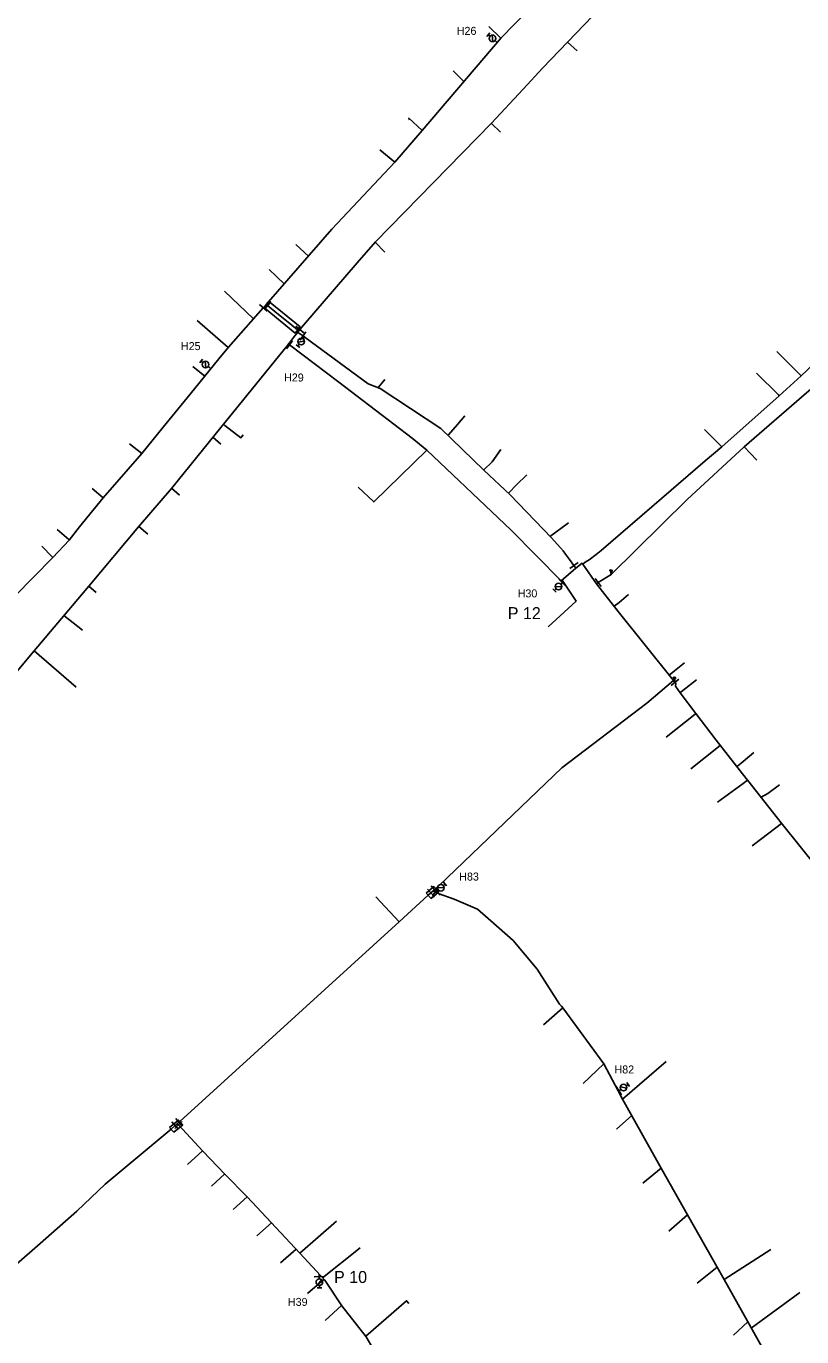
# Model space of a CAD drawing. Extents: x -548873 to -538270, y -1201997 to -1192514.
# Drawn here: x -547306.8 to -547113, y -1195818 to -1195490.5 of the extents above; entities that cross this region are included whole.
import ezdxf

# ---------------------------------------------------------------- set-up
doc = ezdxf.new("R2010")
doc.units = 0
for name, color, linetype in [('KN_HRAN_STÁTNÍ', 7, 'Continuous'), ('KN_PARC_Č', 7, 'Continuous'), ('KN_VKP_HRAN_SPORNÁ', 7, 'Continuous'), ('PK_PARC_Čv', 7, 'Continuous'), ('Vrstva 29', 7, 'Continuous'), ('Vrstva 37', 7, 'Continuous'), ('Vrstva 39', 7, 'Continuous')]:
    doc.layers.add(name, color=color, linetype=linetype)

# ---------------------------------------------------------------- blocks, each defined once
blk = doc.blocks.new('160')
at = {"layer": 'KN_HRAN_STÁTNÍ'}
blk.add_circle((0, 0), 0.0458, dxfattribs=at)
blk = doc.blocks.new('147')
at = {"layer": 'KN_HRAN_STÁTNÍ'}
blk.add_line((0, 1.27), (0, -1.27), dxfattribs=at)
blk = doc.blocks.new('133')
at = {"layer": 'KN_HRAN_STÁTNÍ'}
for p, q in [((0.28, 0), (0, 0)), ((0.54, 0.58), (1.7, -0.58)), ((1.94, 0), (2.52, 0)), ((2.52, 0.58), (2.52, -0.58))]:
    blk.add_line(p, q, dxfattribs=at)
blk.add_circle((1.11, 0), 0.825, dxfattribs=at)
blk = doc.blocks.new('150')
at = {"layer": 'KN_HRAN_STÁTNÍ'}
blk.add_line((0, 1.27), (0, -1.27), dxfattribs=at)
blk = doc.blocks.new('128')
at = {"layer": 'KN_HRAN_STÁTNÍ'}
for p, q in [((-0.19, 1.06), (-0.43, 1.15)), ((-0.36, 0.84), (-0.19, 1.06)), ((-0.19, 1.06), (-0.02, 1.25)), ((-0.19, 1.06), (0, 0)), ((0.05, 0.95), (-0.19, 1.06)), ((-0.1, 1), (0.41, 0.91)), ((-0.07, 0.82), (0.17, 0.96)), ((0.17, 0.96), (-0.02, 1.13)), ((0.17, 0.96), (0, 0)), ((0.19, 1.21), (0.17, 0.96)), ((0.17, 0.96), (0.38, 1.08)), ((0.36, 0.77), (0.17, 0.96))]:
    blk.add_line(p, q, dxfattribs=at)

msp = doc.modelspace()

# ---------------------------------------------------------------- linework, layer by layer
at = {"layer": 'KN_PARC_Č'}
for points in [[(-547188.157, -1195493.496), (-547191.164, -1195490.57)], [(-547171.484, -1195494.463), (-547169.098, -1195496.683)], [(-547197.389, -1195504.339), (-547200.042, -1195501.672)], [(-547207.846, -1195516.619), (-547211.224, -1195513.439)], [(-547211.006, -1195513.645), (-547211.208, -1195513.866)], [(-547190.525, -1195514.821), (-547188.235, -1195516.991)], [(-547214.683, -1195524.509), (-547218.366, -1195521.395)], [(-547236.248, -1195547.97), (-547239.432, -1195545.051)], [(-547219.586, -1195544.48), (-547217.193, -1195546.978)], [(-547242.278, -1195554.859), (-547246.1, -1195551.344)], [(-547250.005, -1195563.656), (-547257.238, -1195556.764)], [(-547256.303, -1195570.794), (-547264.062, -1195564.051)], [(-547113.076, -1195577.902), (-547113.32, -1195577.63), (-547119.159, -1195571.788)], [(-547262.12, -1195577.937), (-547265.145, -1195575.593)], [(-547118.599, -1195582.875), (-547118.81, -1195582.65), (-547124.265, -1195577.19)], [(-547218.844, -1195580.867), (-547218.77, -1195580.697), (-547217.921, -1195579.725), (-547217.128, -1195578.812)], [(-547257.49, -1195589.982), (-547257.128, -1195590.262), (-547253.117, -1195593.362), (-547252.599, -1195592.662)], [(-547201.391, -1195592.725), (-547201.277, -1195592.602), (-547198.998, -1195590.061), (-547197.133, -1195587.91)], [(-547260.139, -1195593.247), (-547258.16, -1195594.956)], [(-547132.96, -1195595.64), (-547133.15, -1195595.4), (-547137.277, -1195591.271)], [(-547277.917, -1195597.331), (-547280.94, -1195594.853)], [(-547206.662, -1195596.428), (-547219.922, -1195609.405), (-547223.845, -1195605.7)], [(-547192.461, -1195601.464), (-547192.379, -1195601.369), (-547190.34, -1195599.362), (-547188.176, -1195596.329)], [(-547127.391, -1195595.645), (-547124.167, -1195598.929)], [(-547186.253, -1195607.23), (-547186.147, -1195607.116), (-547184.212, -1195605.156), (-547181.648, -1195602.627)], [(-547287.52, -1195608.37), (-547290.321, -1195606.042)], [(-547270.481, -1195605.996), (-547268.448, -1195607.715)], [(-547296.04, -1195618.93), (-547296.17, -1195618.82), (-547299.07, -1195616.294)], [(-547278.677, -1195615.583), (-547276.384, -1195617.447)], [(-547175.823, -1195618.078), (-547175.647, -1195617.909), (-547171.622, -1195614.915), (-547171.26, -1195614.594)], [(-547300.1, -1195623.31), (-547300.23, -1195623.18), (-547302.917, -1195620.483)], [(-547172.848, -1195628.94), (-547169.35, -1195634.196), (-547176.358, -1195640.581)], [(-547291.146, -1195630.415), (-547289.296, -1195632.069)], [(-547159.856, -1195635.438), (-547158.582, -1195634.575), (-547156.257, -1195632.55)], [(-547297.369, -1195637.797), (-547292.745, -1195641.468)], [(-547304.795, -1195646.608), (-547294.298, -1195655.699)], [(-547146.057, -1195652.697), (-547144.769, -1195651.626), (-547142.303, -1195649.588)], [(-547143.317, -1195657.085), (-547143.209, -1195656.982), (-547142.65, -1195656.557), (-547139.304, -1195653.845)], [(-547139.408, -1195662.241), (-547139.619, -1195662.409), (-547146.826, -1195668.214)], [(-547133.312, -1195670.243), (-547140.646, -1195676.08)], [(-547129.144, -1195675.573), (-547129.002, -1195675.464), (-547127.61, -1195674.241), (-547124.906, -1195671.996)], [(-547126.535, -1195678.903), (-547127.613, -1195679.76), (-547134, -1195684.464)], [(-547123.134, -1195683.202), (-547123.113, -1195683.187), (-547121.404, -1195682.295), (-547118.494, -1195680.119)], [(-547117.976, -1195689.726), (-547118.051, -1195689.784), (-547122.973, -1195693.533), (-547125.334, -1195695.381)], [(-547213.599, -1195714.36), (-547219.415, -1195708.069)], [(-547172.631, -1195735.835), (-547177.528, -1195740.059)], [(-547162.403, -1195749.852), (-547167.63, -1195754.735)], [(-547157.729, -1195758.622), (-547146.882, -1195749.273)], [(-547155.43, -1195762.759), (-547159.256, -1195766.13)], [(-547262.724, -1195771.598), (-547266.506, -1195774.984)], [(-547257.184, -1195777.291), (-547260.458, -1195780.425)], [(-547148.114, -1195775.919), (-547152.679, -1195779.619)], [(-547251.561, -1195783.065), (-547255.072, -1195786.255)], [(-547141.551, -1195787.544), (-547146.206, -1195791.646)], [(-547245.509, -1195789.544), (-547249.18, -1195792.849)], [(-547238.429, -1195797.125), (-547229.231, -1195789.178)], [(-547239.326, -1195796.164), (-547243.224, -1195799.576)], [(-547232.695, -1195803.29), (-547223.289, -1195795.794)], [(-547132.37, -1195803.712), (-547120.7, -1195796.19)], [(-547134.121, -1195800.628), (-547139.086, -1195804.636)], [(-547232.352, -1195803.659), (-547236.451, -1195807.204)], [(-547125.58, -1195815.872), (-547113.481, -1195806.965)], [(-547227.95, -1195810.243), (-547232.034, -1195813.991)], [(-547221.938, -1195817.9), (-547211.733, -1195809.037), (-547211.124, -1195809.71)], [(-547126.457, -1195814.301), (-547130, -1195817.611)]]:
    msp.add_lwpolyline(points, dxfattribs=at)
at = {"layer": 'KN_VKP_HRAN_SPORNÁ'}
for points in [[(-547246.799, -1195560.024), (-547230.382, -1195541.268), (-547214.699, -1195524.527), (-547207.817, -1195516.586), (-547188.114, -1195493.446), (-547181.403, -1195486.59), (-547175.033, -1195479.774), (-547167.714, -1195471.913), (-547160.967, -1195464.894), (-547143.297, -1195446.062), (-547136.789, -1195436.389), (-547134.548, -1195432.99), (-547127.853, -1195421.088), (-547118.783, -1195405.857), (-547114.117, -1195398.022)], [(-547132.988, -1195449.593), (-547144.079, -1195462.753), (-547150.381, -1195470.964), (-547159.039, -1195481.415), (-547177.635, -1195500.911), (-547182.589, -1195506.258), (-547190.482, -1195514.777), (-547219.522, -1195544.405), (-547224.042, -1195549.648), (-547237.452, -1195565.2), (-547238.39, -1195566.304)], [(-547160.61, -1195627.54), (-547141.63, -1195608.78), (-547127.359, -1195595.616), (-547111.746, -1195582.119), (-547089.115, -1195562.731), (-547061.579, -1195539.141), (-547058.208, -1195536.47), (-547044.74, -1195525.49), (-547042.872, -1195522.421), (-547039.65, -1195513.61), (-547035.807, -1195503.886), (-547031.746, -1195506.151), (-547016.716, -1195514.537), (-547006.025, -1195520.502), (-546990.119, -1195529.563), (-546969.644, -1195542.866)], [(-547167.71, -1195624.93), (-547167.11, -1195624.49), (-547166.098, -1195623.905), (-547164.377, -1195622.558), (-547163.1, -1195621.56), (-547147.98, -1195608.532), (-547137.07, -1195599.13), (-547132.96, -1195595.64), (-547118.599, -1195582.875), (-547113.099, -1195577.925), (-547111.617, -1195576.495), (-547096.74, -1195562.14), (-547090.42, -1195556.45), (-547087.773, -1195554), (-547080.425, -1195547.036), (-547050.942, -1195519.091), (-547050.01, -1195518.153), (-547049.27, -1195517.41)], [(-547293.43, -1195615.64), (-547287.52, -1195608.37), (-547277.91, -1195597.322), (-547272.536, -1195590.724), (-547265.825, -1195582.485), (-547258.649, -1195573.675), (-547256.256, -1195570.737), (-547247.536, -1195560.859)], [(-547247.536, -1195560.859), (-547246.799, -1195560.024)], [(-547246.799, -1195560.024), (-547246.567, -1195560.214)], [(-547246.567, -1195560.214), (-547244.118, -1195562.214), (-547241.335, -1195564.488), (-547239.48, -1195566.003), (-547238.963, -1195566.426), (-547238.689, -1195566.656)], [(-547238.917, -1195566.981), (-547239.942, -1195568.349), (-547241.246, -1195569.957)], [(-547238.689, -1195566.656), (-547238.917, -1195566.981)], [(-547238.917, -1195566.981), (-547238.672, -1195567.191)], [(-547238.39, -1195566.304), (-547238.689, -1195566.656)], [(-547238.672, -1195567.191), (-547238.669, -1195567.193), (-547237.584, -1195567.929)], [(-547237.584, -1195567.929), (-547237.026, -1195568.307), (-547221.297, -1195579.87), (-547218.359, -1195581.064), (-547203.143, -1195591.01), (-547192.423, -1195601.501), (-547185.821, -1195607.631), (-547175.504, -1195618.411), (-547172.626, -1195621.662), (-547172.019, -1195622.42), (-547171.003, -1195623.81), (-547169.907, -1195625.32)], [(-547241.246, -1195569.957), (-547259.588, -1195592.568), (-547270.51, -1195606.032), (-547278.725, -1195615.639), (-547291.147, -1195630.416), (-547304.795, -1195646.608), (-547316.823, -1195660.848), (-547326.873, -1195671.491), (-547331.512, -1195679.088), (-547337.016, -1195684.424), (-547351.223, -1195698.329), (-547357.069, -1195703.944)], [(-547241.246, -1195569.957), (-547241, -1195570.143)], [(-547241, -1195570.143), (-547228.659, -1195579.474), (-547210.315, -1195593.437), (-547206.664, -1195596.426), (-547185.56, -1195616.44), (-547173.09, -1195629.15), (-547169.431, -1195625.977)], [(-547319.87, -1195643.25), (-547319.38, -1195642.78), (-547300.1, -1195623.31), (-547296.04, -1195618.93), (-547293.43, -1195615.64)], [(-547169.907, -1195625.32), (-547169.431, -1195625.977)], [(-547169.431, -1195625.977), (-547167.881, -1195624.72), (-547167.71, -1195624.93)], [(-547167.71, -1195624.93), (-547164.226, -1195629.833)], [(-547164.226, -1195629.833), (-547163.871, -1195629.544)], [(-547164.226, -1195629.833), (-547159.162, -1195636.328)], [(-547163.871, -1195629.544), (-547160.61, -1195627.54)], [(-547159.162, -1195636.328), (-547145.014, -1195653.999)], [(-547145.014, -1195653.999), (-547151.72, -1195659.69), (-547172.901, -1195675.827), (-547203.578, -1195705.232), (-547204.416, -1195706.032), (-547204.473, -1195706.086), (-547204.735, -1195706.318)], [(-547145.014, -1195653.999), (-547144.779, -1195654.323)], [(-547144.779, -1195654.323), (-547144.665, -1195654.487)], [(-547144.665, -1195654.487), (-547144.454, -1195654.703), (-547144.513, -1195655.474), (-547143.317, -1195657.085), (-547139.408, -1195662.241), (-547134.331, -1195668.939), (-547126.864, -1195678.49), (-547126.412, -1195679.057), (-547119.021, -1195688.403), (-547118.07, -1195689.608), (-547108.983, -1195701.041), (-547101.095, -1195711.038), (-547100.661, -1195711.518), (-547094.705, -1195719.024), (-547087.803, -1195727.655), (-547080.248, -1195737.156), (-547076.81, -1195741.454), (-547069.388, -1195750.676), (-547065.365, -1195755.767), (-547059.201, -1195763.374)], [(-547205.625, -1195707.109), (-547206.305, -1195707.713), (-547213.599, -1195714.36), (-547268.366, -1195764.271), (-547268.604, -1195764.47)], [(-547205.057, -1195706.604), (-547205.625, -1195707.109)], [(-547204.735, -1195706.318), (-547205.057, -1195706.604)], [(-547204.638, -1195706.848), (-547205.057, -1195706.604)], [(-547120.307, -1195825.316), (-547132.374, -1195803.704), (-547141.539, -1195787.566), (-547148.053, -1195776.029), (-547157.729, -1195758.622), (-547158.807, -1195756.6), (-547162.403, -1195749.852), (-547172.652, -1195735.806), (-547172.977, -1195735.453), (-547173.481, -1195734.906), (-547179.072, -1195726.137), (-547185.043, -1195719.013), (-547190.689, -1195714.11), (-547194.018, -1195711.149), (-547199.79, -1195708.655), (-547203.551, -1195707.329), (-547204.028, -1195707.156), (-547204.638, -1195706.848)], [(-547268.604, -1195764.47), (-547268.987, -1195764.792)], [(-547269.561, -1195765.274), (-547270.596, -1195766.141), (-547287.035, -1195779.881), (-547294.101, -1195786.683), (-547303.328, -1195794.687), (-547309.862, -1195800.458), (-547311.869, -1195802.1)], [(-547268.987, -1195764.792), (-547269.561, -1195765.274)], [(-547268.987, -1195764.792), (-547268.716, -1195765.086)], [(-547268.716, -1195765.086), (-547262.663, -1195771.664), (-547257.105, -1195777.372), (-547251.547, -1195783.08), (-547238.429, -1195797.125), (-547232.152, -1195803.874), (-547227.937, -1195810.262), (-547221.839, -1195818.026), (-547216.584, -1195827.046)]]:
    msp.add_lwpolyline(points, dxfattribs=at)
at = {"layer": 'PK_PARC_Čv'}
for points in [[(-547189.051, -1195494.547), (-547189.386, -1195494.261)], [(-547237.231, -1195568.168), (-547237.414, -1195568.421)], [(-547260.632, -1195576.11), (-547261.089, -1195575.75)], [(-547172.541, -1195629.401), (-547172.95, -1195629.79)], [(-547206.8, -1195707.19), (-547204.91, -1195705.51), (-547203.68, -1195706.81), (-547205.57, -1195708.49), (-547206.8, -1195707.19)], [(-547204.408, -1195706.964), (-547203.972, -1195706.576)], [(-547158.807, -1195756.6), (-547158.438, -1195756.365)], [(-547270.97, -1195765.75), (-547268.74, -1195763.88), (-547267.64, -1195765.03), (-547269.87, -1195766.9), (-547270.97, -1195765.75)], [(-547233.551, -1195802.37), (-547233.543, -1195803.022), (-547233.54, -1195803.279)]]:
    msp.add_lwpolyline(points, dxfattribs=at)
at = {"layer": 'Vrstva 37'}
msp.add_lwpolyline([(-547245.797, -1195559.552), (-547238.33, -1195565.652), (-547239.596, -1195567.2), (-547247.062, -1195561.101), (-547245.797, -1195559.552)], dxfattribs=at)

# ---------------------------------------------------------------- block references
at = {"layer": 'PK_PARC_Čv'}
for name, p, xscale, yscale, rotation in [('133', (-547189.386, -1195494.261), 1.0000000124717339, 1.0000000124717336, 139.99999868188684), ('133', (-547237.414, -1195568.421), 1.000000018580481, 1.000000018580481, -125.00000023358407), ('133', (-547261.089, -1195575.75), 1.000000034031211, 1.0000000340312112, 141.99999959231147), ('133', (-547172.95, -1195629.79), 1.0000000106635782, 1.0000000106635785, -135.99999834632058), ('150', (-547172.749, -1195629.599), 1.0000000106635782, 1.0000000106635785, 44.00000165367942), ('133', (-547203.972, -1195706.576), 1.0000000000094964, 1.0000000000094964, 42.000001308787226), ('150', (-547204.19, -1195706.77), 1.0000000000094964, 1.0000000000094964, 42.000001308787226), ('133', (-547158.438, -1195756.365), 0.9999999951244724, 0.9999999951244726, 33.000001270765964), ('150', (-547158.693, -1195756.527), 0.9999999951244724, 0.9999999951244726, 33.000001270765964), ('150', (-547233.543, -1195803.022), 1.000000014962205, 1.0000000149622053, 90.99999994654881), ('133', (-547233.54, -1195803.279), 1.000000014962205, 1.0000000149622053, -89.0000000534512)]:
    msp.add_blockref(name, p, dxfattribs=dict(at, xscale=xscale, yscale=yscale, rotation=rotation))
at = {"layer": 'Vrstva 29'}
for name, p, xscale, yscale, rotation in [('147', (-547247.536, -1195560.859), 1.0000000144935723, 1.0000000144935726, 49.00000089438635), ('147', (-547246.567, -1195560.214), 1.000000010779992, 1.0000000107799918, 141.00000108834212), ('160', (-547246.799, -1195560.024), 1.000000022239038, 1.0000000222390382, 94.99999998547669), ('147', (-547238.39, -1195566.304), 1.0000000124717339, 1.0000000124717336, 49.99999868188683), ('160', (-547238.917, -1195566.981), 0.9999999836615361, 0.9999999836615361, 98.00000038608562), ('160', (-547238.689, -1195566.656), 0.9999999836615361, 0.9999999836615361, -81.99999961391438), ('147', (-547237.584, -1195567.929), 0.9999999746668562, 0.999999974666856, 145.99999954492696), ('147', (-547241, -1195570.143), 0.9999999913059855, 0.9999999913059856, 142.99999806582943), ('160', (-547241.246, -1195569.957), 1.0098116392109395, 1.0098116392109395, 10.610301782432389), ('147', (-547169.907, -1195625.32), 1.000000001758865, 1.000000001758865, 125.99999933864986), ('160', (-547169.431, -1195625.977), 1.0000000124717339, 1.0000000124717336, 40.00000131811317), ('160', (-547167.71, -1195624.93), 1.0000000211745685, 1.0000000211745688, -98.99999960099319), ('147', (-547163.871, -1195629.544), 1.000000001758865, 1.000000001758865, -144.00000066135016), ('160', (-547164.226, -1195629.833), 0.9999999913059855, 0.9999999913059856, -52.999998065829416), ('160', (-547160.61, -1195627.54), 1.000000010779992, 1.0000000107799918, -141.00000108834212), ('160', (-547159.162, -1195636.328), 1.000000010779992, 1.0000000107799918, 128.99999891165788), ('147', (-547144.665, -1195654.487), 1.0000000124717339, 1.0000000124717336, 130.0000013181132), ('160', (-547145.014, -1195653.999), 1.000000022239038, 1.0000000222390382, -94.99999998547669), ('160', (-547144.779, -1195654.323), 1.000000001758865, 1.000000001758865, 125.99999933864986), ('147', (-547204.735, -1195706.318), 1.0000000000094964, 1.0000000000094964, -137.9999986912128), ('147', (-547205.625, -1195707.109), 1.0000000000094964, 1.0000000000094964, -137.9999986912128), ('147', (-547204.638, -1195706.848), 1.0072562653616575, 1.0072562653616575, -28.76666512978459), ('160', (-547205.057, -1195706.604), 1.0011217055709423, 1.0011217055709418, 6.582609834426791), ('147', (-547269.561, -1195765.274), 1.0000000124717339, 1.0000000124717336, 40.00000131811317), ('147', (-547268.716, -1195765.086), 1.00000000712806, 1.00000000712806, 133.00000056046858), ('147', (-547268.604, -1195764.47), 1.0000000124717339, 1.0000000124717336, -139.99999868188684), ('160', (-547268.987, -1195764.792), 0.9999999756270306, 0.9999999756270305, 86.99999998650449)]:
    msp.add_blockref(name, p, dxfattribs=dict(at, xscale=xscale, yscale=yscale, rotation=rotation))
at = {"layer": 'Vrstva 39'}
for p in [(-547160.61, -1195627.54), (-547144.779, -1195654.323)]:
    msp.add_blockref('128', p, dxfattribs=at)

# ---------------------------------------------------------------- texts
at = {"layer": 'PK_PARC_Čv'}
for s, height, p in [('H26', 2, (-547199.176, -1195492.681)), ('H25', 2, (-547268.119, -1195571.46)), ('H29', 2, (-547242.334, -1195579.301)), ('H30', 2, (-547183.96, -1195633.26)), ('P 12', 3, (-547186.43, -1195638.7)), ('H83', 2, (-547198.562, -1195704.026)), ('H82', 2, (-547159.758, -1195752.235)), ('P 10', 3, (-547229.85, -1195804.599)), ('H39', 2, (-547241.38, -1195810.319))]:
    msp.add_text(s, height=height, dxfattribs=at).set_placement(p)

doc.saveas('drawing.dxf')
